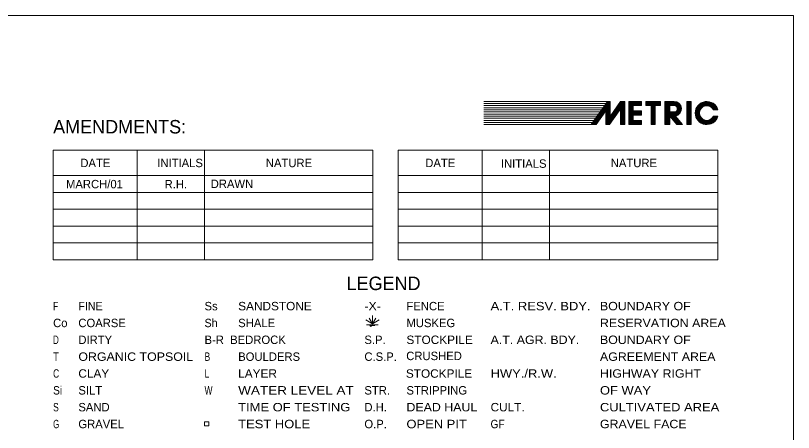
# Model space of a CAD drawing. Extents: x -496 to 480, y -450 to 700.
# Drawn here: x -12.3 to 450, y 452.5 to 700 of the extents above; entities that cross this region are included whole.
import ezdxf
from ezdxf.enums import TextEntityAlignment as Align

# ---------------------------------------------------------------- set-up
doc = ezdxf.new("R2010")
doc.units = 0
doc.header["$LTSCALE"] = 2
doc.header["$PDMODE"] = 32
doc.header["$PDSIZE"] = 1
doc.layers.add('1', color=7, linetype='Continuous', lineweight=13)

msp = doc.modelspace()

# ---------------------------------------------------------------- linework, layer by layer
at = {"layer": '1'}
for p, q in [((339.376, 648.989), (265.976, 648.989)), ((338.501, 647.739), (265.976, 647.739)), ((329.726, 635.239), (339.376, 648.989)), ((340.976, 640.064), (347.226, 648.989)), ((349.726, 648.989), (347.226, 648.989)), ((349.726, 635.239), (349.726, 648.989)), ((362.226, 648.989), (362.226, 646.489)), ((379.026, 648.989), (373.476, 648.989)), ((337.626, 646.489), (265.976, 646.489)), ((336.751, 645.239), (265.976, 645.239)), ((335.876, 643.989), (265.976, 643.989)), ((335.001, 642.739), (265.976, 642.739)), ((332.776, 635.239), (338.476, 643.364)), ((338.476, 635.239), (338.476, 643.389)), ((340.676, 635.264), (347.226, 644.614)), ((347.226, 635.239), (347.226, 644.614)), ((354.726, 646.489), (354.726, 643.364)), ((362.226, 646.489), (365.351, 646.489)), ((367.851, 646.489), (370.976, 646.489)), ((376.601, 646.489), (379.151, 646.489)), ((376.601, 642.739), (376.601, 646.489)), ((376.601, 642.739), (379.151, 642.739)), ((402.426, 643.989), (405.076, 643.989)), ((334.126, 641.489), (265.976, 641.489)), ((333.251, 640.239), (265.976, 640.239)), ((332.376, 638.989), (265.976, 638.989)), ((354.726, 640.864), (354.726, 637.739)), ((376.601, 640.239), (380.726, 635.239)), ((376.601, 635.239), (376.601, 640.239)), ((379.801, 640.289), (383.951, 635.239)), ((402.426, 640.239), (405.101, 640.239)), ((331.501, 637.739), (265.976, 637.739)), ((330.626, 636.489), (265.976, 636.489)), ((329.726, 635.239), (265.976, 635.239)), ((329.726, 635.239), (332.776, 635.239)), ((338.476, 635.239), (340.676, 635.239)), ((349.726, 635.239), (347.226, 635.239)), ((352.226, 635.239), (359.726, 635.239)), ((380.726, 635.239), (383.951, 635.239)), ((199.983, 619.973), (9.983, 619.973)), ((9.983, 619.973), (9.983, 554.973)), ((59.983, 619.973), (59.983, 554.973)), ((99.983, 619.973), (99.983, 554.973)), ((199.983, 554.973), (199.983, 619.973)), ((404.983, 619.973), (214.983, 619.973)), ((214.983, 619.973), (214.983, 554.973)), ((264.983, 619.973), (264.983, 554.973)), ((304.983, 619.973), (304.983, 554.973)), ((404.983, 554.973), (404.983, 619.973)), ((9.983, 604.973), (199.983, 604.973)), ((214.983, 604.973), (404.983, 604.973)), ((9.983, 594.973), (199.983, 594.973)), ((214.983, 594.973), (404.983, 594.973)), ((9.983, 584.973), (199.983, 584.973)), ((214.983, 584.973), (404.983, 584.973)), ((9.983, 574.973), (199.983, 574.973)), ((214.983, 574.973), (404.983, 574.973)), ((9.983, 564.973), (199.983, 564.973)), ((214.983, 564.973), (404.983, 564.973)), ((214.983, 554.973), (404.983, 554.973)), ((199.76, 516.875), (195.76, 519.375)), ((199.76, 516.875), (197.76, 520.375)), ((199.76, 516.875), (199.76, 521.875)), ((199.76, 516.875), (201.76, 520.375)), ((199.76, 516.875), (203.76, 519.375)), ((196.26, 516.375), (203.26, 516.375)), ((198.26, 515.875), (201.26, 515.875))]:
    msp.add_line(p, q, dxfattribs=at)
for points in [[(449.983, -450.027), (449.983, 399.973), (449.983, 699.973), (-450.017, 699.973), (-450.017, 49.973), (-450.017, -450.027)], [(329.901, 635.339), (339.401, 648.889), (340.901, 648.889), (340.901, 639.839), (347.251, 648.839), (349.626, 648.889), (349.676, 635.339), (347.351, 635.314), (347.301, 644.789), (340.576, 635.339), (338.576, 635.314), (338.576, 643.539), (332.701, 635.339), (330.076, 635.314), (339.501, 648.739), (340.801, 648.739), (340.776, 639.664), (347.276, 648.664), (349.526, 648.739), (349.651, 635.564), (347.501, 635.464), (347.426, 644.989), (340.526, 635.489), (338.726, 635.439), (338.676, 643.764), (332.651, 635.464), (330.301, 635.439), (339.576, 648.539), (340.651, 648.564), (340.651, 639.489), (347.351, 648.489), (349.301, 648.564), (349.476, 635.739), (347.726, 635.639), (347.626, 645.314), (340.451, 635.714), (338.926, 635.639), (338.876, 644.139), (332.501, 635.689), (330.701, 635.639)], [(330.701, 635.639), (339.651, 648.239), (340.326, 648.264), (340.476, 639.239), (347.526, 648.239), (349.126, 648.289), (349.226, 635.939), (348.001, 635.939), (347.851, 645.664), (340.326, 635.989), (339.151, 635.864), (339.126, 644.464), (332.401, 635.939), (331.076, 635.839), (339.651, 647.914), (340.151, 647.914), (340.251, 638.889), (347.601, 647.964), (348.926, 648.014), (349.026, 636.164), (348.251, 636.139), (348.051, 646.014), (340.226, 636.239), (339.351, 636.089), (339.326, 644.789), (332.226, 636.164), (331.476, 636.064), (339.701, 647.664), (339.926, 647.689), (340.126, 638.764), (347.751, 647.839), (348.701, 647.739), (348.826, 636.364), (348.476, 636.364), (348.176, 646.314), (340.126, 636.464), (339.551, 636.339), (339.426, 645.114), (332.201, 636.339), (331.851, 636.289)], [(331.851, 636.289), (339.701, 647.264), (339.926, 638.564), (347.826, 647.614), (348.451, 647.589), (348.701, 636.589), (348.251, 646.639), (340.126, 636.689), (339.726, 636.589), (339.576, 645.539), (332.301, 636.639), (339.526, 646.714), (339.576, 645.814), (335.101, 640.239), (339.401, 646.164), (339.401, 645.914), (338.176, 644.289)], [(340.976, 640.039), (340.976, 648.989), (339.376, 648.989)], [(339.901, 638.414), (339.926, 636.839), (348.276, 646.889), (348.326, 647.439), (347.951, 647.439), (340.126, 638.539), (340.151, 637.314), (348.176, 647.064), (348.051, 647.214), (340.326, 638.539), (340.401, 637.839), (347.851, 646.839), (340.501, 638.639), (340.526, 638.389), (344.426, 642.914)], [(352.226, 635.239), (352.226, 648.989), (359.726, 648.989)], [(352.376, 648.914), (359.651, 648.864), (359.676, 646.614), (354.626, 646.589), (354.626, 643.289), (359.651, 643.289), (359.651, 640.989), (354.651, 640.939), (354.626, 637.614), (359.676, 637.639), (359.651, 635.339), (352.351, 635.314), (352.376, 648.789), (359.551, 648.739), (359.551, 646.764), (354.501, 646.714), (354.501, 643.214), (359.551, 643.164), (359.551, 641.114), (354.551, 641.064), (354.526, 637.439), (359.551, 637.514), (359.501, 635.439), (352.501, 635.439), (352.576, 648.639), (359.401, 648.564), (359.426, 646.914), (354.376, 646.839), (354.351, 643.064), (359.426, 643.039), (359.376, 641.289), (354.401, 641.239), (354.376, 637.239), (359.401, 637.339), (359.376, 635.589), (352.701, 635.614), (352.726, 648.439), (359.226, 648.414), (359.251, 647.064), (354.251, 647.039)], [(354.251, 647.039), (354.176, 642.864), (359.251, 642.864), (359.176, 641.439), (354.251, 641.389), (354.201, 637.064), (359.201, 637.114), (359.176, 635.739), (352.926, 635.814), (352.976, 648.214), (359.026, 648.239), (359.076, 647.289), (354.076, 647.214), (354.001, 642.689), (359.051, 642.664), (359.026, 641.639), (354.076, 641.564), (354.026, 636.864), (359.051, 636.939), (359.026, 635.989), (353.126, 636.039), (353.226, 647.989), (358.801, 648.039), (358.826, 647.464), (353.926, 647.389), (353.851, 642.489), (358.876, 642.539), (358.801, 641.814), (353.951, 641.689), (353.851, 636.714), (358.901, 636.764), (358.901, 636.214), (353.351, 636.214), (353.476, 647.714), (358.601, 647.889), (358.626, 647.639), (353.776, 647.514), (353.751, 642.364), (358.626, 642.389), (358.601, 642.014)], [(358.601, 642.014), (353.826, 641.864), (353.726, 636.564), (358.701, 636.639), (358.701, 636.389), (353.551, 636.439), (353.626, 641.989), (358.376, 642.164), (358.326, 642.289), (353.576, 642.264), (353.676, 647.564)], [(359.726, 648.989), (359.726, 646.489), (354.726, 646.489)], [(370.976, 646.489), (370.976, 648.989), (362.226, 648.989)], [(362.351, 648.864), (370.851, 648.889), (370.851, 646.639), (367.701, 646.639), (367.751, 635.414), (365.451, 635.314), (365.451, 646.564), (362.351, 646.589), (362.351, 648.764), (370.801, 648.789), (370.726, 646.789), (367.601, 646.764), (367.676, 635.539), (365.576, 635.414), (365.626, 646.739), (362.476, 646.739), (362.476, 648.639), (370.626, 648.639), (370.576, 646.989), (367.426, 646.864), (367.526, 635.739), (365.751, 635.614), (365.776, 646.864), (362.701, 646.939), (362.726, 648.439), (370.451, 648.489), (370.376, 647.114), (367.276, 646.989), (367.376, 635.914), (365.901, 635.789), (365.951, 647.064), (362.901, 647.114), (362.901, 648.264), (370.201, 648.289), (370.201, 647.364), (367.076, 647.189), (367.226, 636.114), (366.126, 635.989), (366.101, 647.264), (363.101, 647.314)], [(363.101, 647.314), (363.151, 648.089), (369.976, 648.164), (369.926, 647.489), (366.876, 647.364), (367.026, 636.339), (366.351, 636.239), (366.276, 647.439), (363.326, 647.514), (363.401, 647.939), (369.751, 648.039), (369.701, 647.714), (366.726, 647.539), (366.851, 636.564), (366.476, 636.489), (366.426, 647.664), (363.701, 647.664), (363.751, 647.839), (369.451, 647.914), (369.426, 647.814), (366.601, 647.664), (366.626, 636.689)], [(373.476, 648.989), (373.476, 635.239), (376.601, 635.239)], [(373.601, 648.914), (378.976, 648.889), (380.101, 648.739), (381.101, 648.364), (381.826, 647.789), (382.451, 647.189), (382.901, 646.414), (383.301, 645.389), (383.301, 644.439), (383.126, 643.214), (382.651, 642.314), (381.926, 641.489), (381.051, 640.889), (380.401, 640.639), (379.651, 640.389), (380.026, 639.714), (380.576, 639.189), (383.701, 635.339), (380.801, 635.314), (376.501, 640.464), (376.526, 635.339), (373.551, 635.314), (373.551, 648.864), (379.026, 648.789), (380.076, 648.639), (380.926, 648.314), (382.276, 647.214), (383.151, 645.364), (383.026, 643.314), (382.601, 642.464), (381.901, 641.614), (381.051, 640.989), (379.576, 640.464), (383.501, 635.414), (380.951, 635.439), (376.351, 640.739), (376.401, 635.489), (373.701, 635.439), (373.701, 648.739), (379.151, 648.664), (380.076, 648.489), (380.851, 648.189), (382.126, 647.139), (383.026, 645.389), (382.951, 643.539), (382.501, 642.564), (381.901, 641.739), (381.051, 641.114), (379.401, 640.614), (383.201, 635.564), (381.001, 635.564), (376.226, 640.889), (376.276, 635.614), (373.826, 635.539), (373.826, 648.614), (379.126, 648.489), (380.676, 648.089), (382.026, 647.139), (382.876, 645.439), (382.801, 643.664), (382.401, 642.664), (381.801, 641.889), (380.951, 641.189), (379.226, 640.764), (382.901, 635.689), (381.101, 635.689), (376.051, 641.064), (376.126, 635.789), (373.976, 635.689), (373.976, 648.439), (379.101, 648.364), (380.551, 647.989), (381.851, 647.089), (382.776, 645.439), (382.701, 643.764), (382.326, 642.889), (381.726, 642.064), (380.901, 641.339), (379.026, 640.939), (382.601, 635.789), (381.126, 635.814), (375.876, 641.239), (375.976, 635.939), (374.126, 635.864), (374.126, 648.239), (379.026, 648.239), (380.251, 647.914), (381.676, 647.014), (382.576, 645.414), (382.601, 643.914), (382.276, 642.989), (381.651, 642.214), (380.826, 641.514), (378.851, 641.064), (382.351, 635.939), (381.176, 635.989), (375.776, 641.514), (375.826, 636.089), (374.251, 636.014), (374.276, 648.039), (378.976, 648.114)], [(378.976, 648.114), (379.026, 648.114), (380.201, 647.764), (381.526, 646.939), (382.401, 645.489), (382.401, 643.964), (382.076, 643.114), (380.826, 641.764), (378.601, 641.264), (382.001, 636.114), (381.351, 636.114), (375.676, 641.789), (375.676, 636.264), (374.376, 636.189), (374.451, 647.864), (378.926, 647.939), (380.176, 647.689), (381.351, 646.914), (382.151, 645.414), (382.201, 644.014), (381.901, 643.214), (380.726, 641.989), (378.401, 641.389), (381.676, 636.314), (381.501, 636.189), (375.526, 642.064), (375.476, 636.414), (374.551, 636.339), (374.651, 647.739), (379.976, 647.614), (381.151, 646.914), (382.001, 645.414), (382.051, 644.139), (381.726, 643.339), (380.651, 642.139), (378.226, 641.589), (381.401, 636.464), (375.401, 642.364), (375.376, 636.614), (374.676, 636.539), (374.901, 647.589), (379.826, 647.414), (380.851, 646.889), (381.801, 645.439), (381.901, 644.389), (381.576, 643.539), (380.576, 642.414), (378.051, 641.739), (380.676, 637.364), (375.376, 642.614), (375.226, 636.739), (374.851, 636.739), (375.076, 647.339), (379.601, 647.314), (380.676, 646.839), (381.626, 645.414), (381.726, 644.464), (381.376, 643.589), (380.501, 642.589), (377.826, 641.864), (380.026, 638.189), (375.251, 642.889), (375.076, 636.939), (374.926, 636.989), (375.226, 647.189), (379.526, 647.139), (380.551, 646.714), (381.401, 645.414), (381.551, 644.614), (380.376, 642.739), (377.726, 642.039), (379.276, 639.239), (375.351, 643.039), (375.426, 646.989), (379.476, 646.989), (380.526, 646.639), (381.251, 645.489), (381.326, 644.614), (380.276, 642.914), (377.551, 642.239), (378.601, 640.139), (375.576, 643.139), (375.676, 646.839), (379.451, 646.839), (380.476, 646.514), (381.101, 645.414), (381.051, 644.489), (380.876, 645.464), (380.501, 646.039), (380.151, 646.339), (379.476, 646.514), (378.751, 646.639), (377.601, 646.614), (376.476, 646.614), (376.501, 642.714), (378.626, 642.664), (377.376, 642.339), (378.126, 640.764), (375.726, 643.164), (375.876, 646.714), (379.451, 646.714)], [(386.776, 648.839), (388.951, 648.864), (389.001, 635.364), (386.701, 635.364), (386.676, 648.739), (388.851, 648.764), (388.876, 635.489), (386.826, 635.439), (386.801, 648.614), (388.776, 648.639), (388.776, 635.664), (386.976, 635.589), (386.926, 648.464), (388.626, 648.464), (388.601, 635.764), (387.126, 635.764), (387.101, 648.364), (388.501, 648.364), (388.451, 635.939), (387.301, 635.964), (387.301, 648.214), (388.401, 648.214), (388.301, 636.089), (387.426, 636.089), (387.476, 648.064), (388.251, 648.039), (388.151, 636.214), (387.576, 636.214), (387.676, 647.914), (388.126, 647.889), (388.001, 636.339), (387.776, 636.389), (387.826, 647.764), (387.976, 647.714), (387.901, 636.539)], [(404.901, 644.089), (404.451, 645.189), (403.851, 646.164), (403.151, 646.914), (402.301, 647.639), (401.151, 648.289), (400.126, 648.614), (398.801, 648.814), (397.351, 648.689), (395.876, 648.339), (394.601, 647.639), (393.601, 646.764), (392.776, 645.664), (392.176, 644.564), (391.801, 642.964), (391.801, 641.264), (392.176, 639.789), (392.726, 638.564), (393.351, 637.739), (394.101, 637.014), (394.976, 636.389), (395.901, 635.914), (397.126, 635.489), (398.726, 635.389), (400.151, 635.589), (401.301, 635.989), (402.326, 636.564), (403.326, 637.414), (404.001, 638.264), (404.426, 639.139), (404.801, 640.064), (402.526, 640.089), (401.776, 638.989), (400.776, 638.289), (399.801, 637.814), (398.476, 637.564), (397.026, 637.839), (396.126, 638.289), (395.276, 638.939), (394.551, 639.939), (394.076, 641.189), (394.051, 642.814), (394.276, 643.889), (394.901, 644.889), (395.601, 645.614), (396.476, 646.164), (397.376, 646.489), (398.426, 646.614), (399.526, 646.489), (400.426, 646.214), (401.176, 645.764), (401.801, 645.239), (402.301, 644.664), (402.576, 644.139), (404.726, 644.164), (404.251, 645.214), (403.651, 646.164), (402.276, 647.489), (401.126, 648.114), (399.351, 648.614), (397.876, 648.564), (396.551, 648.339), (395.226, 647.814), (394.351, 647.264), (393.451, 646.339), (392.676, 645.139), (392.176, 643.939), (391.976, 642.239), (392.076, 640.689), (392.576, 639.164), (393.476, 637.864), (394.526, 636.864), (395.701, 636.164), (397.201, 635.639), (398.626, 635.514), (400.251, 635.764), (401.276, 636.089), (402.301, 636.789), (403.176, 637.439), (403.726, 638.164), (404.376, 639.239), (404.551, 639.964), (402.626, 639.989), (402.076, 639.064), (400.751, 638.139), (399.826, 637.689), (398.526, 637.389), (396.976, 637.739), (395.601, 638.439), (394.651, 639.639), (394.076, 640.764), (393.876, 642.139), (394.151, 643.989), (394.726, 644.964), (395.826, 646.014), (397.051, 646.539), (398.351, 646.789), (399.826, 646.614), (401.026, 646.064), (401.701, 645.614), (402.226, 645.014)], [(402.226, 645.014), (402.301, 645.014), (402.676, 644.239), (404.476, 644.264), (404.026, 645.314), (402.876, 646.664), (401.901, 647.489), (400.851, 648.089), (399.251, 648.514), (396.976, 648.264), (395.201, 647.614), (394.051, 646.639), (393.151, 645.614), (392.526, 644.239), (392.176, 642.439), (392.326, 640.539), (392.676, 639.489), (392.951, 638.864), (393.701, 637.864), (394.851, 636.839), (397.101, 635.814), (398.651, 635.664), (401.026, 636.164), (403.076, 637.564), (403.901, 638.814), (404.326, 639.814), (403.476, 639.789), (402.726, 639.839), (402.201, 638.889), (400.776, 637.964), (399.526, 637.414), (398.251, 637.264), (396.651, 637.714), (395.476, 638.364), (394.451, 639.714), (393.901, 640.864), (393.701, 642.264), (393.976, 643.889), (394.651, 645.264), (395.701, 646.214), (397.376, 646.789), (398.851, 646.914), (400.251, 646.614), (401.626, 645.914), (402.426, 645.164), (402.801, 644.439), (404.226, 644.414), (403.426, 645.739), (402.676, 646.614), (401.826, 647.314), (400.851, 647.939), (399.276, 648.314), (397.051, 648.089), (395.226, 647.364), (393.976, 646.314), (393.201, 645.414), (392.651, 643.839), (392.426, 642.514), (392.451, 641.239), (392.651, 640.089), (393.101, 639.039), (393.651, 638.239), (394.376, 637.564), (395.226, 636.839), (396.351, 636.314), (397.451, 635.914), (398.701, 635.839), (400.826, 636.364), (402.976, 637.639), (403.801, 638.964), (404.026, 639.714), (402.851, 639.664), (402.326, 638.814), (401.226, 638.164), (399.651, 637.239), (398.226, 637.114), (397.101, 637.389), (395.976, 637.889), (394.801, 638.989), (394.101, 640.014), (393.601, 641.664), (393.676, 643.264), (394.101, 644.689), (395.376, 646.214), (396.876, 646.764), (398.751, 647.064), (400.326, 646.764), (401.751, 646.089), (402.651, 645.189), (402.951, 644.539), (403.876, 644.614), (403.051, 645.989), (402.201, 646.789), (400.851, 647.739), (399.376, 648.189), (397.151, 647.889), (395.451, 647.239), (394.076, 646.164), (393.251, 645.039), (392.701, 643.014), (392.651, 641.564)], [(392.651, 641.564), (392.676, 641.614), (392.951, 639.914), (393.451, 638.964), (394.051, 638.214), (394.926, 637.289), (395.951, 636.764), (396.601, 636.389), (397.801, 636.039), (398.776, 635.989), (400.726, 636.464), (402.951, 637.739), (403.651, 639.064), (403.726, 639.564), (403.026, 639.539), (402.576, 638.814), (399.876, 637.114), (398.026, 637.014), (396.051, 637.664), (394.476, 639.139), (393.526, 641.439), (393.651, 643.889), (394.476, 645.514), (395.726, 646.539), (397.351, 646.989), (398.701, 647.239), (400.476, 646.939), (401.751, 646.339), (402.526, 645.664), (402.851, 645.114), (403.076, 644.739), (403.551, 644.789), (402.926, 645.989), (401.801, 646.914), (400.676, 647.639), (399.376, 648.039), (397.176, 647.789), (395.676, 647.164), (394.226, 646.139), (393.501, 645.039), (392.901, 643.314), (392.826, 641.639), (393.126, 639.989), (393.851, 638.689), (394.951, 637.514), (396.001, 636.989), (396.726, 636.564), (398.626, 636.139), (400.701, 636.614), (402.776, 637.864), (403.476, 639.064), (403.601, 639.464), (403.251, 639.389), (402.751, 638.739), (400.001, 637.014), (398.001, 636.889), (395.901, 637.564), (394.326, 639.064), (393.376, 641.464), (393.576, 643.939), (394.301, 645.589), (395.526, 646.689), (398.576, 647.339), (400.751, 647.089), (401.751, 646.489), (402.601, 645.914), (403.076, 645.039), (403.326, 644.914), (402.851, 645.939), (400.926, 647.289), (399.526, 647.889), (397.401, 647.714), (395.626, 647.039), (394.251, 646.039), (393.576, 644.889), (393.026, 643.239), (392.951, 641.714), (393.276, 640.314), (393.801, 639.139), (394.376, 638.339), (395.076, 637.639), (396.901, 636.764), (398.651, 636.314), (400.576, 636.789), (402.601, 637.914), (403.351, 639.139), (402.501, 638.339), (401.601, 637.789), (400.101, 636.864), (398.051, 636.764), (395.801, 637.439), (394.176, 639.064), (393.226, 641.539), (393.501, 644.014), (394.126, 645.639), (395.451, 646.739), (397.026, 647.189), (398.576, 647.489), (399.776, 647.389), (400.526, 647.289), (399.551, 647.639)], [(399.551, 647.639), (398.601, 647.639), (397.451, 647.489), (395.901, 647.064)], [(354.726, 640.864), (359.726, 640.864), (359.726, 643.364), (354.726, 643.364)], [(367.851, 646.489), (367.851, 635.239), (365.351, 635.239), (365.351, 646.489)], [(376.026, 646.614), (375.901, 643.214), (377.551, 641.614), (377.251, 642.364), (377.776, 642.614), (376.826, 642.614), (377.201, 642.164)], [(376.151, 646.564), (376.051, 643.314), (376.376, 643.064), (376.351, 646.564), (376.251, 643.389)], [(379.451, 646.714), (379.401, 646.739), (380.451, 646.289)], [(402.751, 638.439), (402.076, 637.814), (400.676, 637.089), (399.226, 636.639), (398.501, 636.639), (396.951, 636.914), (395.751, 637.364), (394.201, 638.764), (393.101, 641.589), (393.401, 643.964), (393.901, 645.289)], [(354.726, 637.739), (359.726, 637.739), (359.726, 635.239)], [(9.983, 554.973), (99.983, 554.973), (199.983, 554.973)]]:
    msp.add_lwpolyline(points, dxfattribs=at)
for points in [[(386.601, 635.239), (386.601, 648.989), (389.101, 648.989), (389.101, 635.239)], [(99.967, 456.301), (99.967, 458.832), (102.499, 458.832), (102.499, 456.301)]]:
    msp.add_lwpolyline(points, close=True, dxfattribs=at)
for centre, radius, start, end in [((379.076, 644.614), 4.375, 279.51602, 90.65478), ((398.476, 642.114), 6.875, 15.80251, 344.19749), ((379.051, 644.614), 1.875, 272.29061, 86.94712), ((398.476, 642.114), 4.375, 25.39292, 334.60708)]:
    msp.add_arc(centre, radius, start, end, dxfattribs=at)
msp.add_point((198.76, 515.875), dxfattribs=at)

# ---------------------------------------------------------------- texts
for s, height, p in [('AMENDMENTS:', 8, (9.983, 629.973)), ('Ss', 5, (99.983, 524.973)), ('FENCE', 5, (219.983, 524.973)), ('Co', 5, (9.983, 514.973)), ('COARSE', 5, (24.983, 514.973)), ('SHALE', 5, (119.983, 514.973)), ('MUSKEG', 5, (219.983, 514.973)), ('DIRTY', 5, (24.983, 504.973)), ('B-R  BEDROCK', 5, (99.983, 504.973)), ('S.P.', 5, (194.983, 504.973)), ('BOULDERS', 5, (119.983, 494.973)), ('C.S.P.', 5, (194.983, 494.973)), ('CRUSHED', 5, (219.856, 495.402)), ('SILT', 5, (24.983, 474.973)), ('STR.', 5, (194.983, 474.973)), ('STRIPPING', 5, (219.983, 474.973)), ('SAND', 5, (24.983, 464.973)), ('D.H.', 5, (194.983, 464.973)), ('GRAVEL', 5, (24.983, 454.973)), ('O.P.', 5, (194.983, 454.973))]:
    msp.add_text(s, height=height, dxfattribs=at).set_placement(p)
for s, height, p in [('DATE', 5, (35.081, 609.973)), ('INITIALS', 5, (85.453, 609.973)), ('NATURE', 5, (150.16, 609.973)), ('DATE', 5, (240.081, 609.973)), ('NATURE', 5, (355.16, 609.973)), ('INITIALS', 5, (289.66, 609.584)), ('MARCH/01', 5, (34.552, 597.405)), ('R.H.', 5, (82.941, 597.343)), ('DRAWN', 5, (116.266, 597.567)), ('LEGEND', 8, (206.378, 536.973))]:
    msp.add_text(s, height=height, dxfattribs=at).set_placement(p, align=Align.CENTER)
for s, width, p in [('F', 0.75, (9.983, 524.973)), ('FINE', 0.95, (24.983, 524.973)), ('SANDSTONE', 1.05, (119.983, 524.973)), ('-X-', 1.1, (194.983, 524.973)), ('A.T. RESV. BDY.', 1.15, (269.983, 524.973)), ('BOUNDARY OF', 1.1, (334.983, 524.973)), ('Sh', 0.95, (99.983, 514.973)), ('RESERVATION AREA', 1.1, (334.983, 514.973)), ('D', 0.7, (9.983, 504.973)), ('STOCKPILE', 1.05, (219.983, 504.973)), ('A.T. AGR. BDY.', 1.1, (269.983, 504.973)), ('BOUNDARY OF', 1.1, (334.983, 504.973)), ('T', 0.85, (9.983, 494.973)), ('ORGANIC TOPSOIL', 1.1, (24.983, 494.973)), ('B', 0.75, (99.983, 494.973)), ('AGREEMENT AREA', 1.1, (334.983, 494.973)), ('HWY./R.W.', 1.15, (269.983, 484.973)), ('C', 0.75, (9.983, 484.973)), ('CLAY', 1.05, (24.983, 484.973)), ('L', 0.75, (99.983, 484.973)), ('LAYER', 1.05, (119.983, 484.973)), ('STOCKPILE', 1.05, (219.649, 484.941)), ('HIGHWAY RIGHT', 1.1, (334.983, 484.973)), ('Si', 0.9, (9.983, 474.973)), ('W', 0.75, (99.983, 474.973)), ('WATER LEVEL AT', 1.2, (119.983, 474.973)), ('OF WAY', 1.15, (334.983, 474.973)), ('S', 0.75, (9.983, 464.973)), ('TIME OF TESTING', 1.15, (119.983, 464.973)), ('DEAD HAUL', 1.1, (219.983, 464.973)), ('CULT.', 1.05, (269.983, 464.973)), ('CULTIVATED AREA', 1.15, (334.983, 464.973)), ('G', 0.7, (9.983, 454.973)), ('TEST HOLE', 1.15, (119.983, 454.973)), ('OPEN PIT', 1.15, (219.983, 454.973)), ('GF', 0.9, (269.983, 454.973)), ('GRAVEL FACE', 1.1, (334.983, 454.973))]:
    msp.add_text(s, height=5, dxfattribs=dict(at, width=width)).set_placement(p)

doc.saveas('drawing.dxf')
